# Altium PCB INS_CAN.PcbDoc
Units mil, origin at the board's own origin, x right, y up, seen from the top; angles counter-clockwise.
Board outline 1181.1 x 1181.1 mil, 2 copper layers (Top Layer, Bottom Layer), stack 62.992 mil thick; 50 components, 37 nets, 209 pads, 111 vias.
Unrouted connection lines stored in the file: 32.
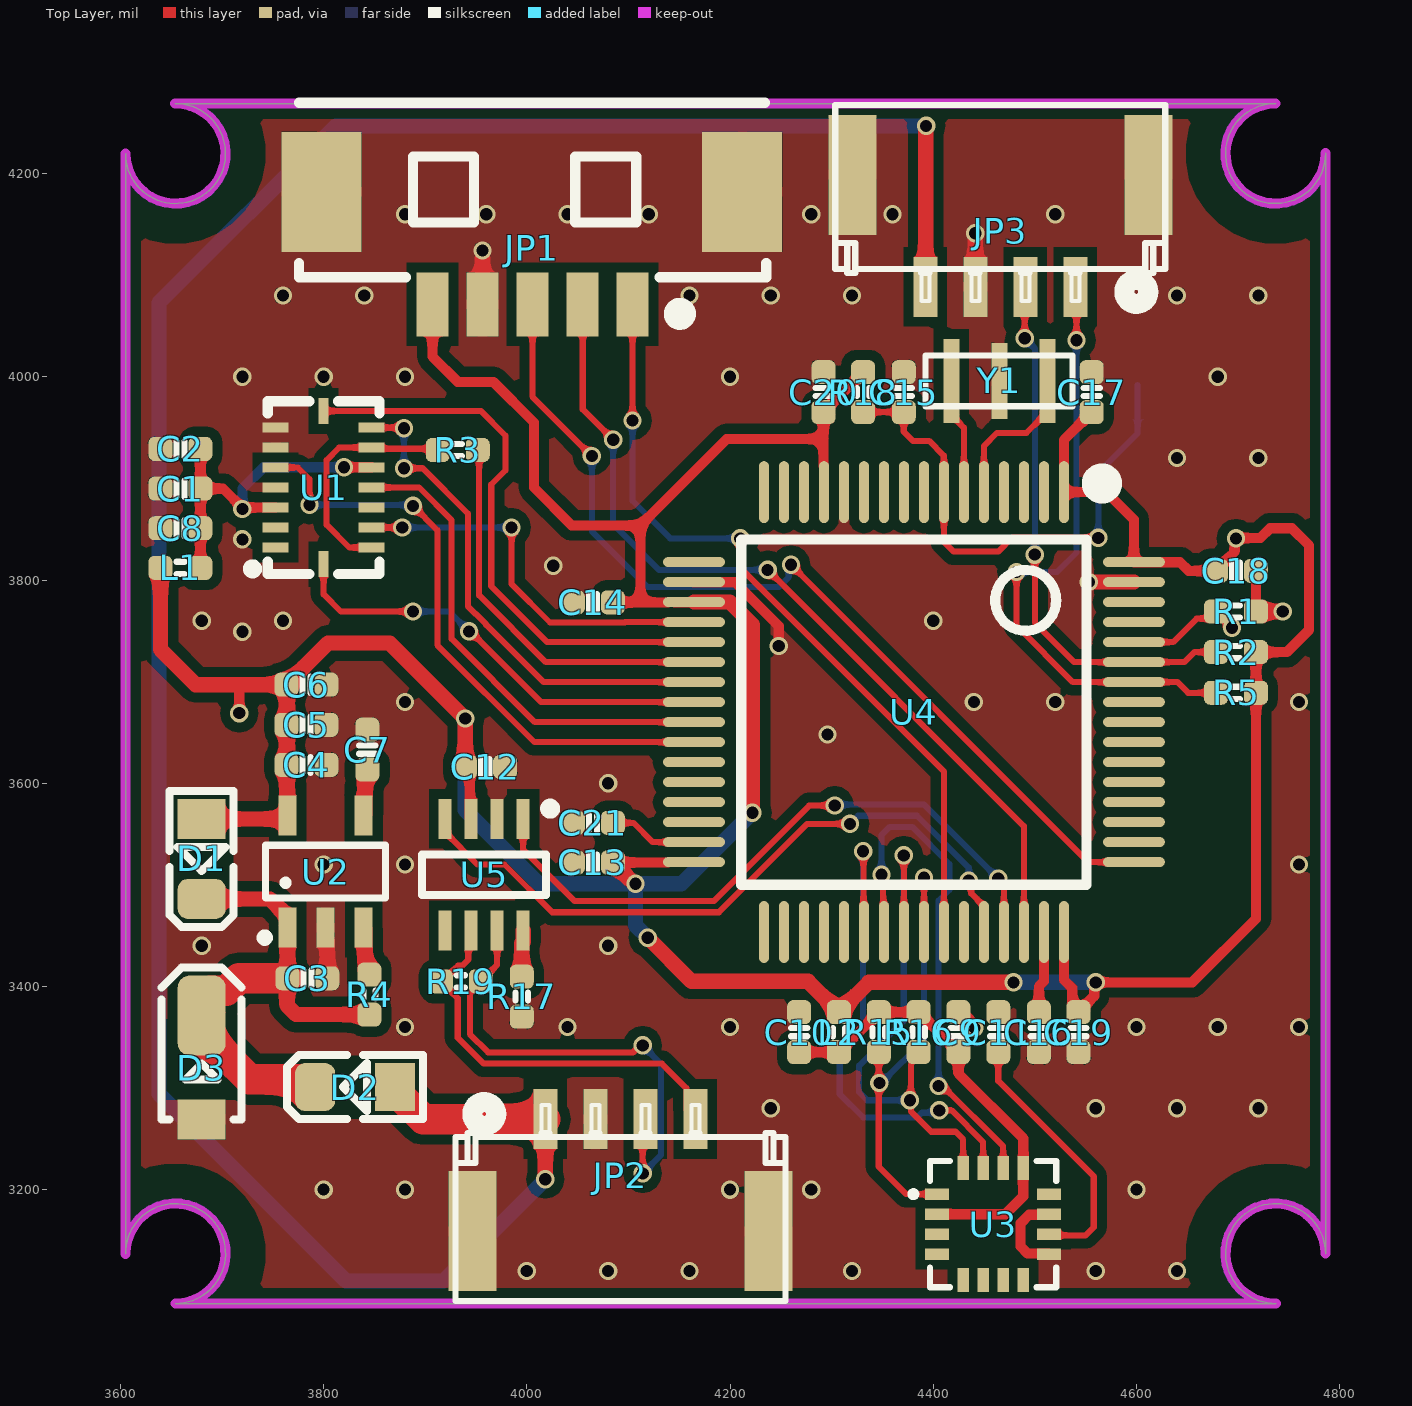
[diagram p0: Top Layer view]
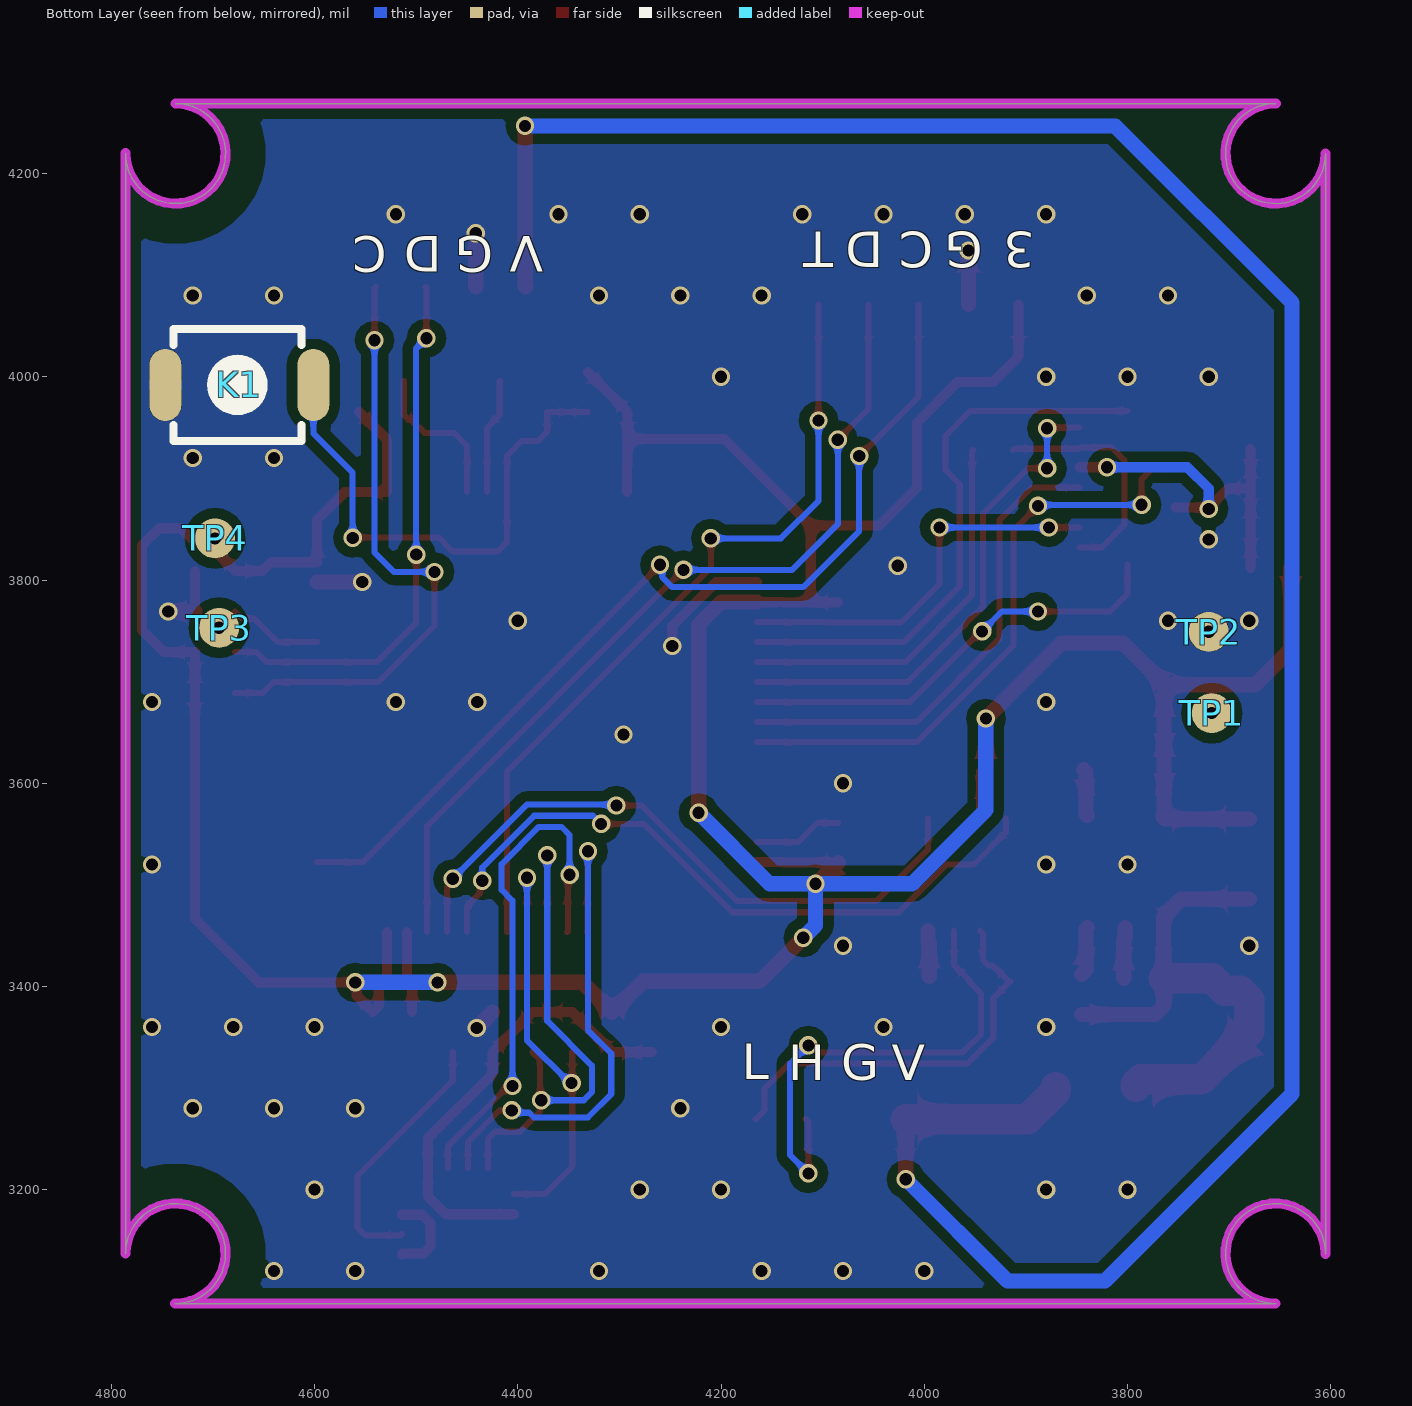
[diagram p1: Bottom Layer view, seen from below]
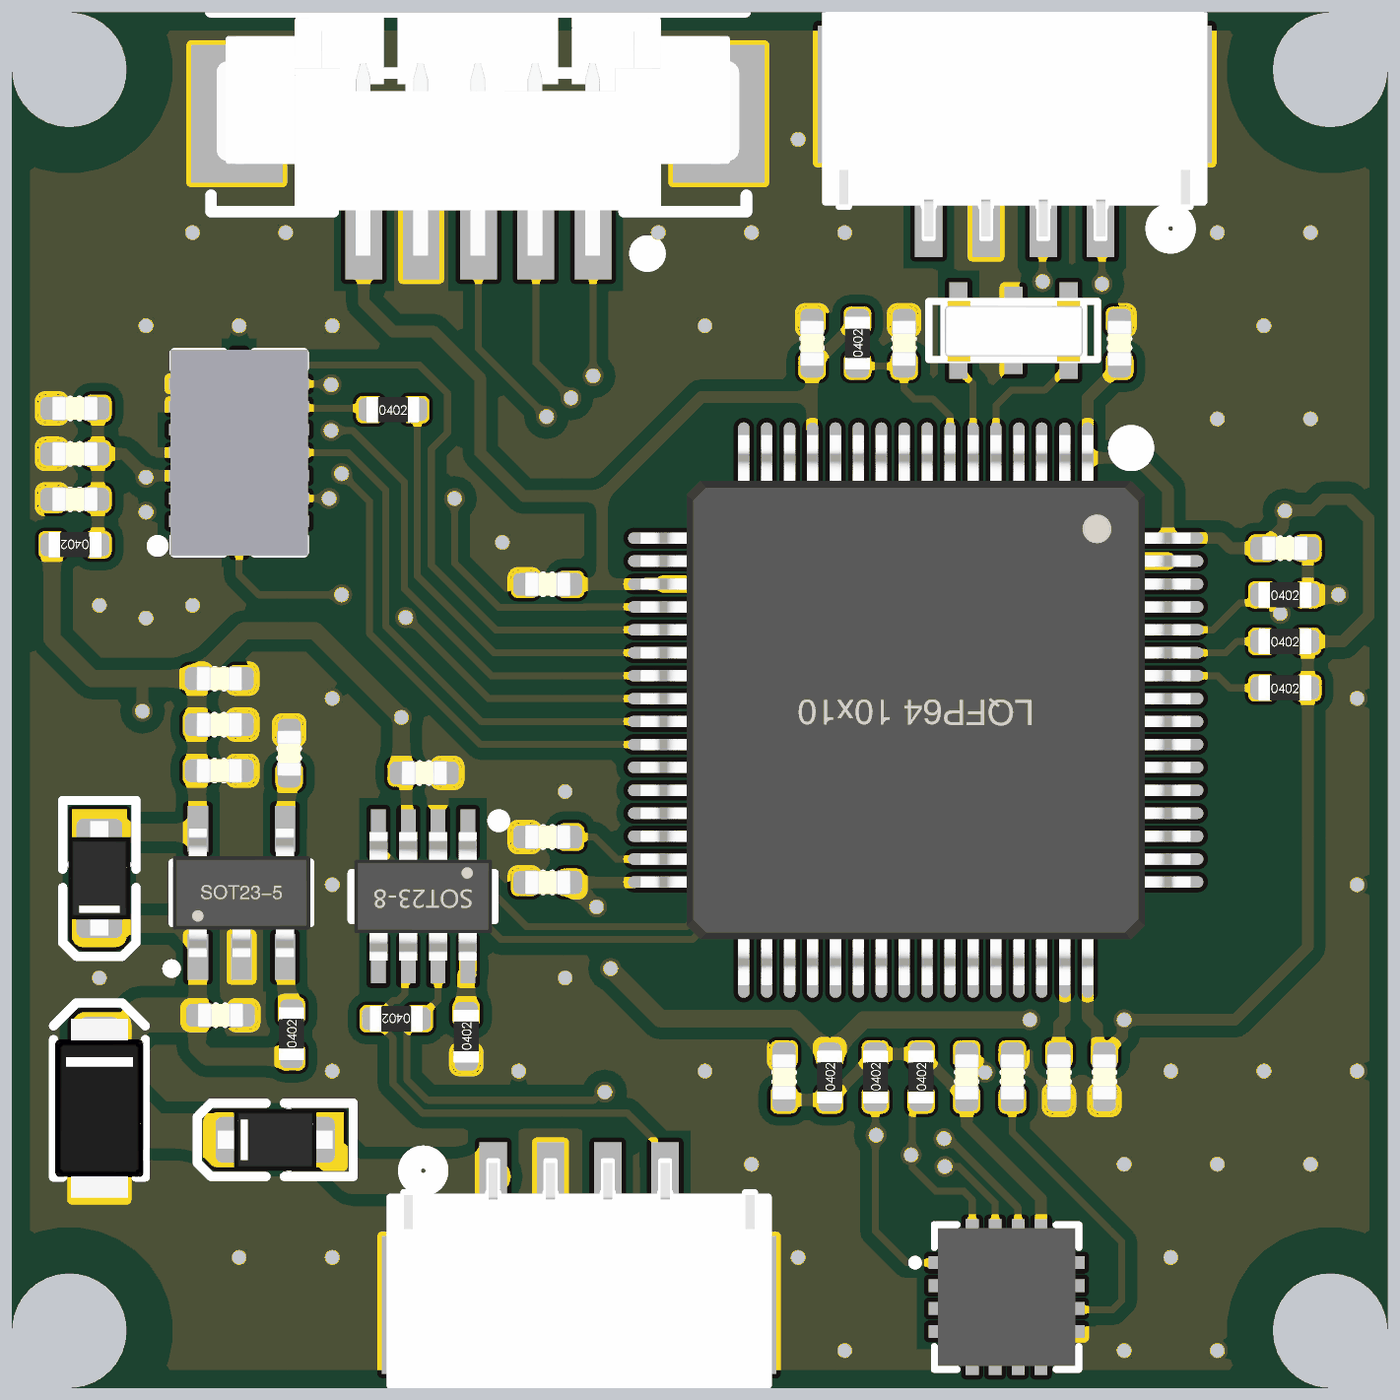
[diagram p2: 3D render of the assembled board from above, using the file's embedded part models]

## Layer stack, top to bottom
Top Solder: solder mask 0.4, Solder Resist, Dk 3.5
Top Layer: signal copper 1.9685
Dielectric 1: dielectric 59.0551, FR-4, Dk 4.8
Bottom Layer: signal copper 1.9685
Bottom Solder: solder mask 0.4, Solder Resist, Dk 3.5

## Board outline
3605,3136.9 3605,4219.79 ccw(c3654.21,4219.79) 3654,4269 4736.89,4269 ccw(c4736.89,4219.79) 4786.1,4220 4786.1,3137.11 ccw(c4736.89,3137.11) 4737.1,3087.9 3654.21,3087.9 ccw(c3654.21,3137.11)

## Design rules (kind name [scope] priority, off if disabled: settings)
AssemblyTestPointUsage [All] p1 off:
AssemblyTestpoint [All] p1 off: testpointundercomponent=TRUE minsize=40 maxsize=100 preferedsize=60 minholesize=0 maxholesize=40 preferedholesize=32 testpointgrid=1 usegrid=TRUE gridtolerance=0.01 allowsidetop=TRUE allowsidebottom=TRUE
Clearance Clearance_1 [InPolygon] p1: gap=10 ignorepadtopadclearanceinfootprint=FALSE
Clearance [All] p2: gap=5 ignorepadtopadclearanceinfootprint=FALSE
ComponentClearance [All] p1 off: gap=10 collisioncheckmode=3 verticalgap=10 showdistances=FALSE
DiffPairsRouting [All] p1 off: maxlimit=10 minlimit=6 mostfreqgap=6 toplayer_minwidth=6 toplayer_maxwidth=15 toplayer_prefwidth=6 bottomlayer_minwidth=6 bottomlayer_maxwidth=15 bottomlayer_prefwidth=6 maxuncoupledlength=500
FabricationTestPointUsage [All] p1 off: valid=0 allowmultiple=FALSE
FabricationTestpoint [All] p1 off: side=3 testpointundercomponent=TRUE minsize=40 maxsize=100 preferedsize=60 minholesize=0 maxholesize=40 preferedholesize=32 testpointgrid=1 allowsidetop=TRUE allowsidebottom=TRUE usegrid=TRUE gridtolerance=0.01
FanoutControl Fanout_BGA [IsBGA] p1 off: bgadir=Out bgaviamode=Centered fanoutstyle=Auto fanoutdirection=Alternating viagrid=1 // Fanout_BGA (Default Rule)
FanoutControl Fanout_LCC [IsLCC] p2 off: bgadir=Out bgaviamode=Centered fanoutstyle=Auto fanoutdirection=Alternating viagrid=1 // Fanout_LCC (Default Rule)
FanoutControl Fanout_SOIC [IsSOIC] p3 off: bgadir=Out bgaviamode=Centered fanoutstyle=Auto fanoutdirection=Alternating viagrid=1 // Fanout_SOIC (Default Rule)
FanoutControl Fanout_Small [(CompPinCount < 5)] p4 off: bgadir=Out bgaviamode=Centered fanoutstyle=Auto fanoutdirection=OutThenIn viagrid=1 // Fanout_Small (Default Rule)
FanoutControl Fanout_Default [All] p5 off: bgadir=Out bgaviamode=Centered fanoutstyle=Auto fanoutdirection=Alternating viagrid=1 // Fanout_Default (Default Rule)
Height [All] p1 off: minheight=0 maxheight=1000 prefheight=500
HoleSize [All] p1 off: absolutevalues=TRUE maxlimit=100 minlimit=1 maxpercent=80.000 minpercent=20.000
HoleToHoleClearance [All] p1 off: gap=10 allowstackedmicrovias=TRUE
LayerPairs [All] p1 off: enforce=TRUE
MinimumSolderMaskSliver [All] p1 off: minsoldermaskwidth=10
NetAntennae [All] p1 off: netantennaetolerance=0
PasteMaskExpansion [All] p1 off: expansion=0
PlaneClearance [All] p1 off: clearance=30
PlaneConnect [All] p1 off: planeconnectstyle=Direct reliefexpansion=10 reliefentries=4 reliefconductorwidth=10 reliefairgap=5
PolygonConnect [All] p1 off: connectstyle=Direct reliefconductorwidth=10 reliefentries=4 polygonreliefangle="90 Angle" airgapwidth=10
RoutingCorners [All] p1 off: cornerstyle=45-Degree minsetback=100 maxsetback=100
RoutingLayers [All] p1 off: top layer_v5=TRUE bottom layer_v5=TRUE
RoutingPriority [All] p1 off: routingpriority=0
RoutingTopology [All] p1 off: topology=Shortest
RoutingVias [All] p1 off: holewidth=10 width=18 viastyle="Through Hole" minholewidth=5 minwidth=5 maxholewidth=100 maxwidth=100
SilkToSilkClearance [All] p1 off: silktosilkclearance=10
SilkToSolderMaskClearance [IsPad] p1 off: minsilkscreentomaskgap=10 clearancetoexposedcopper=TRUE
SolderMaskExpansion [All] p1 off: expansion=4 istentingtop=FALSE
Width [All] p1 off: maxlimit=1000 minlimit=5 preferedwidth=10
4 further rules are at their usual default settings.

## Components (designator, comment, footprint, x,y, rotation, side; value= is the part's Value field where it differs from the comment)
C1 "10uF" C0402 3659,3890 r180 top value=0.1u
C2 "0.1uF" C0402 3659,3929 r180 top value=0.1u
C3 "1uF/25V" C0402 3784,3408 r180 top value=0.1u
C4 "0.1uF/50V" C0402 3783,3618 r180 top value=0.1u
C5 "1uF/25V" C0402 3783,3657.5 r180 top value=0.1u
C6 "0.1uF/50V" C0402 3783,3697 r180 top value=0.1u
C7 "10nF/50V" C0402 3843,3633 r270 top value=0.1u
C8 "0.1uF" C0402 3659,3851 r180 top value=0.1u
C9 "0.1uF" C0402 4424.8,3355 r90 top value=0.1u
C10 "0.1uF" C0402 4268,3355 r90 top value=0.1u
C11 "4.7uF" C0402 4464,3355 r90 top value=0.1u
C12 "0.1uF/50V" C0402 3959,3616 r180 top value=0.1u
C13 "0.1uF" C0402 4065,3522 r180 top value=0.1u
C14 "0.1uF" C0402 4065,3778 r180 top value=0.1u
C15 "0.1uF/50V" C0402 4371,3985 r270 top value=0.1u
C16 "2.2uF" C0402 4504,3355 r270 top value=0.1u
C17 "0.1uF" C0402 4556,3985 r90 top value=0.1u
C18 "0.1uF" C0402 4698,3809 r0 top value=0.1u
C19 "0.1uF" C0402 4543,3355 r270 top value=0.1u
C20 "0.1uF" C0402 4292,3985 r90 top value=0.1u
C21 "2.2uF" C0402 4065,3561 r180 top value=0.1u
D1 "1N5819" D_SOD323 3680,3525.5 r270 top
D2 "1N5819" D_SOD323 3831,3301 r180 top
D3 "SMFJ5.0A" D_SOD123A 3680,3328 r90 top
JP1 "HDR-1X5" "MX 1.25-WS-5P" 4005,4182 r180 top
JP2 "SWD" GH1.25-WS-4P 4092,3171 r180 top
JP3 "SWD" GH1.25-WS-4P 4466,4187 r0 top
K1 "6x6x5" SWPBS_SPST_3X2X1 4676,3992 r180 bottom
L1 "60R 25% 3A" R0402 3659,3812 r180 top
L2 "60R 25% 3A" R0402 4307.2,3355 r90 top
R1 "10K" R0402 4698,3769 r0 top value=22R
R2 "4.7K" R0402 4698,3729 r0 top value=22R
R3 "33R" R0402 3932,3928 r0 top value=22R
R4 "100K" R0402 3845,3392 r90 top value=22R
R5 "4.7K" R0402 4698,3689 r0 top value=22R
R15 "4.7K" R0402 4346.4,3355 r90 top value=22R
R16 "4.7K" R0402 4385.6,3355 r90 top value=22R
R17 "0R" R0402 3995,3390 r90 top value=22R
R18 "10K" R0402 4331,3985 r90 top value=22R
R19 "120R/NC" R0402 3935,3405 r180 top value=22R
TP1 "TEST" "TEST 1" 3717,3669 r270 bottom
TP2 "TEST" "TEST 1" 3720,3749 r270 bottom
TP3 "TEST" "TEST 1" 4694,3753 r0 bottom
TP4 "TEST" "TEST 1" 4698,3841 r0 bottom
U1 "BMI088" "QFN16 BMI" 3800,3891 r0 top
U2 "LP5907 3V3" SOT23-5L 3802,3513 r0 top
U3 "IST8310" QFN50_16T_3X3_IST 4459,3166 r270 top
U4 "STM32F405RGT6V" "LQFP64 10x10_L" 4381,3670 r180 top
U5 "MAX3051EKA+T" SOT23-8L 3958,3510 r180 top
Y1 "8MHz" CSTCE3213 4437.24,3921 r270 top

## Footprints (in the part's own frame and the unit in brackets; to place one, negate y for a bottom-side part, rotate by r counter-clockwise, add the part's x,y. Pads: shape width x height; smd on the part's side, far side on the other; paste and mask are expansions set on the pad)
C0402 [mm] "CHIP Capacitor, 1.0X0.5mm, 0402"
  rrect50% 0.6x0.6 smd paste-0.05 mask+0.075: 1(-0.5,0) 2(0.5,0)
  silkscreen extent -0.1,-0.2 0.1,0.2, body extent -0.5,-0.26 0.5,0.27, height 0.36
CSTCE3213 [mm]
  rect 2.1x0.4 smd: 1(-1.905,1.905) 3(-1.905,-0.495)
  rect 1.9x0.4 smd: 2(-1.905,0.705)
  silkscreen extent -2.54,-1.14 -1.27,2.54, body extent -2.55,-0.89 -1.23,2.31, height 0.9
D_SOD123A [mm] "PowerDI-123, SOD123, DO-213AA, 1206D"
  rect 1x1.2 smd paste-0.1 mask+0.1: 1(-1.5,0)
  rrect50% 2x1.2 smd paste-0.1 mask+0.1: 2(1.1,0)
  Top Layer pour cut-out: -1.016,1.1 -1.016,-1.1 1.016,-1.1 1.016,1.1
  silkscreen extent -1.5,-1 2.3,1, body extent -1.95,-0.97 1.95,0.96, height 1
D_SOD323 [mm] "DIODE0805, SOD-323, SC-76, DL-35, 0805 similar size"
  rect 1x1.2 smd paste-2 mask+0.075: 1(-1,0)
  rrect50% 1x1.2 smd paste-2 mask+0.075: 2(1,0)
  Top Layer pour cut-out: -0.5,0.8 0.5,0.8 0.5,-0.8 -0.5,-0.8
  silkscreen extent -1.7,-0.8 1.7,0.8, body extent -1.25,-0.68 1.25,0.67, height 1
GH1.25-WS-4P [mm] "A1257WR-S-4P"
  rect 1.2x3 smd: 0(-3.7,0.3) 0(3.7,0.3)
  rect 0.6x1.5 smd: 1(1.875,-2.5) 2(0.625,-2.5) 3(-0.625,-2.5) 4(-1.875,-2.5)
  silkscreen extent -4.13,-2.93 4.12,2.05, body extent -4.12,-2.8 4.12,2.1, height 4.4
"LQFP64 10x10_L" [mm] "64脚，体宽10x10mm，脚距0.5mm"
  oval 0.25x1.55 smd: 1(-3.75,-5.5) 2(-3.25,-5.5) 3(-2.75,-5.5) 4(-2.25,-5.5) 5(-1.75,-5.5) 6(-1.25,-5.5) 7(-0.75,-5.5) 8(-0.25,-5.5) 9(0.25,-5.5) 10(0.75,-5.5) 11(1.25,-5.5) 12(1.75,-5.5) 13(2.25,-5.5) 14(2.75,-5.5) 15(3.25,-5.5) 16(3.75,-5.5) 33(3.75,5.5) 34(3.25,5.5) 35(2.75,5.5) 36(2.25,5.5) 37(1.75,5.5) 38(1.25,5.5) 39(0.75,5.5) 40(0.25,5.5) 41(-0.25,5.5) 42(-0.75,5.5) 43(-1.25,5.5) 44(-1.75,5.5) 45(-2.25,5.5) 46(-2.75,5.5) 47(-3.25,5.5) 48(-3.75,5.5)
  oval 1.55x0.25 smd: 17(5.5,-3.75) 18(5.5,-3.25) 19(5.5,-2.75) 20(5.5,-2.25) 21(5.5,-1.75) 22(5.5,-1.25) 23(5.5,-0.75) 24(5.5,-0.25) 25(5.5,0.25) 26(5.5,0.75) 27(5.5,1.25) 28(5.5,1.75) 29(5.5,2.25) 30(5.5,2.75) 31(5.5,3.25) 32(5.5,3.75) 49(-5.499,3.75) 50(-5.499,3.25) 51(-5.499,2.75) 52(-5.499,2.25) 53(-5.499,1.75) 54(-5.499,1.25) 55(-5.499,0.75) 56(-5.499,0.25) 57(-5.499,-0.25) 58(-5.499,-0.75) 59(-5.499,-1.25) 60(-5.499,-1.75) 61(-5.499,-2.25) 62(-5.499,-2.75) 63(-5.499,-3.25) 64(-5.499,-3.75)
  silkscreen extent -4.95,-5.96 4.32,4.32, body extent -6,-6 6,6, height 1.45
"MX 1.25-WS-5P" [mm] "长：11.4mm，宽：4.2mm，高：3.4mm"
  rect 2x3 smd: 0(-5.257,0) 0(5.257,0)
  rect 0.8x1.6 smd: 1(-2.514,2.811) 2(-1.264,2.811) 3(-0.014,2.811) 4(1.236,2.811) 5(2.486,2.811)
  silkscreen extent -5.86,-2.23 5.83,3.25, body extent -5.7,-2.1 5.7,3.09, height 3.4
"QFN16 BMI" [mm] "16脚，长x宽x高：4x4x0.8mm，脚距：0.65mm"
  rect 0.65x0.25 smd: 1(-1.2,-1.498) 2(-1.2,-0.998) 3(-1.2,-0.498) 4(-1.2,0.002) 5(-1.2,0.502) 6(-1.2,1.002) 7(-1.2,1.502) 9(1.2,1.502) 10(1.2,1.002) 11(1.2,0.502) 12(1.2,0.002) 13(1.2,-0.498) 14(1.2,-0.998) 15(1.2,-1.498)
  rect 0.25x0.65 smd: 8(0,1.915) 16(0,-1.915)
  silkscreen extent -1.89,-2.16 1.4,2.16, body extent -1.5,-2.25 1.5,2.25, height 0.88
QFN50_16T_3X3_IST [mm] "RGT PVQFN (TI), 16-lead, pitch: 0.5mm, 3x3mm"
  rect 0.28x0.6 smd: 1(-0.75,-1.4) 2(-0.25,-1.4) 3(0.25,-1.4) 4(0.75,-1.4) 9(0.75,1.4) 10(0.25,1.4) 11(-0.25,1.4) 12(-0.75,1.4)
  rect 0.6x0.28 smd: 5(1.4,-0.75) 6(1.4,-0.25) 7(1.4,0.25) 8(1.4,0.75) 13(-1.4,0.75) 14(-1.4,0.25) 15(-1.4,-0.25) 16(-1.4,-0.75)
  silkscreen extent -1.58,-2.07 1.58,1.58, body extent -1.5,-1.5 1.5,1.5, height 1
R0402 [mm] "CHIP Resistor, 1.0X0.5mm, 0402"
  rrect50% 0.6x0.6 smd paste-0.05 mask+0.075: 1(-0.5,0) 2(0.5,0)
  silkscreen extent -0.1,-0.15 0.1,0.15, body extent -0.57,-0.27 0.58,0.28, height 0.41
SOT23-5L [mm] "3x1.6x1.1mm(长宽高)"
  rect 0.45x1 smd: 1(-0.95,-1.4) 2(0,-1.4) 3(0.95,-1.4) 4(0.95,1.4) 5(-0.95,1.4)
  silkscreen extent -1.6,-1.73 1.5,0.66, body extent -1.5,-1.4 1.5,1.4, height 1.15
SOT23-8L [mm] "3x1.6x1.1mm(长宽高)"
  rect 0.325x1 smd: 1(-0.975,-1.397) 2(-0.325,-1.397) 3(0.325,-1.397) 4(0.975,-1.397) 5(0.975,1.397) 6(0.325,1.397) 7(-0.325,1.397) 8(-0.975,1.397)
  silkscreen extent -1.78,-1.78 1.55,0.51, body extent -1.5,-1.4 1.5,1.4, height 1.15
SWPBS_SPST_3X2X1 [mm] "SWITCH, PUSHBUTTON, SMD, SPST, 3X2.5mm"
  oval 0.8x1.8 smd mask+0.1: 1(-1.8,0) 2(1.9,0)
  silkscreen extent -1.6,-1.4 1.6,1.4, body extent -2,-1.25 2,1.25, height 1.6
"TEST 1" [mm] "测试点1mm"
  round 1 smd paste-1: 1(0,0)

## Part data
C1 C2 C3 C4 C5 C6 C7 C8 C9 C10 C11 C12 C13 C14 C15 C16 C17 C18 C19 C20 C21: library part 电容-0402, "Capacitor"
D1 D2: library part Diode_SMA, "Diode"
D3: library part SMBJ28CA
JP1: library part "Header 5", "5P接插件"
JP2 JP3: library part "Header 1*4"
K1: library part "TSW DIP-6x6_V", "侧按直插6x6轻触开关"
L1 L2: library part L, "小功率贴片电感"
R1 R2 R3 R4 R5 R15 R16 R17 R18 R19: library part 电阻-0402, "Resistor"
TP1 TP2 TP3 TP4: "测试点"
U1: BOM_JLCPCB Part Class="Extended Part", BOM_Manufacturer="Bosch Sensortec"
U2: library part LP2992, "LDO"
U4: JLCPCB Part Class=扩展库, Manufacturer=ST(意法半导体)
U5: BOM_JLCPCB Part Class="Extended Part", BOM_Manufacturer=MAXIM
Y1: library part 晶振-3Pin, "村田贴片"

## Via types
v1: diameter 18, hole 12, Top Layer to Bottom Layer, tented both sides, 111 vias

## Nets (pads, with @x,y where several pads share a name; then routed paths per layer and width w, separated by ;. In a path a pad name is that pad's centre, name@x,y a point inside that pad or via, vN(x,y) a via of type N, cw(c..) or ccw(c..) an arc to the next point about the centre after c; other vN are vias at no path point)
3V3: C4.2 C5.2 C6.2 C12.2 C13.1 C14.1 C17.1 C18.1 C19.1 C20.1 D1.1 JP1.5 L1.2 L2.2 R2.2 R5.2 R18.2 TP1.1 TP4.1 U2.5 U4.1 U4.13 U4.19 U4.32 U4.48 U4.64 U5.3 | length 4124
  Top Layer w10: v1(3717,3669) 3717,3695.34 3718.66,3697 ; JP1.5 3907.12,4019.88 3932,3995 3967,3995 4007,3955 4007,3891 4044.27,3853.73 4111.73,3853.73 ; C12.2 3943.81,3611.51 3943.81,3566.4 U5.3 ; C13.1 4138.67,3522 4139.04,3522.37 U4.32 ; C14.1 4111.73,3778 ; U4.19 4139.04,3778.27 4138.77,3778 4111.73,3778 ; U4.13 4292.41,3911.96 4292,3912.36 4292,3938.84 ; R18.2 4331,4004.5 4292,3965.5 C20.1 4292,3938.84 ; U4.48 4528.63,3406.37 4536.75,3398.25 4536.75,3380.94 C19.1 4543,3375.18 4558.47,3390.64 4558.47,3402.47 v1(4560,3404) 4655,3404 4717.69,3466.68 R5.2 R2.2 4748,3729 4770,3751 4770,3834 4753,3851 4731.58,3851 4722,3841.42 4698.42,3841.42 v1(4698,3841) 4696.47,3839.47 4696.47,3827.64 4678.31,3809.49 C18.1 4651.5,3809 4642.94,3817.56 4597.59,3817.56 U4.64 4597.51,3859.49 4570.48,3886.52 U4.1 4528.63,3937.94 C17.1 ; 4111.73,3778 4111.73,3853.73 ; 4111.73,3853.73 4196.84,3938.84 4292,3938.84
  Top Layer w15: L1.2 3639.32,3731.68 3674,3697 3718.66,3697 C6.2 ; D1.1 3763.24,3564.87 3764.6,3566.23 U2.5 3763.96,3568.76 3763.96,3696.36 C6.2 ; C12.2 v1(3939.32,3663.68) 3865,3738 3804.32,3738 C6.2 ; C13.1 4105.11,3501.57 4106.43,3501.57 v1(4107,3501) ; v1(4119,3448) 4162,3405 4276.89,3405 L2.2 4336.52,3404 v1(4479,3404) ; U4.19 4199.73,3778.27 4222,3756 v1(4222,3571)
  Bottom Layer w15: v1(3939.32,3663.68) 3939.32,3573.68 4012,3501 v1(4107,3501) ; v1(4119,3448) 4107,3460 v1(4107,3501) ; v1(4222,3571) 4152,3501 v1(4107,3501) ; v1(4479,3404) v1(4560,3404)
5V: C3.2 D1.2 D2.2 D3.2 R4.1 U2.1 | length 524.6
  Top Layer w15: D1.2 3747.18,3486.13 3764.46,3468.85 3764.46,3408.14 C3.2 3764,3407.68 3764,3381.1 3772.79,3372.32 R4.1
  Top Layer w30: C3.2 3716.69,3408 3704.37,3395.68 3688.62,3395.68 3680,3387.06 D3.2 3680,3355.56 3726.94,3308.61 3786.94,3308.61 3791.63,3303.93 D2.2
AS_SCL: JP3.1 R5.1 U4.58 | length 605.6
  Top Layer w6: v1(4482,3808) 4482,3755 4537.47,3699.53 U4.58 4640.47,3699.53 4651,3689 R5.1 ; JP3.1 4541,4087.39 v1(4541,4036)
  Bottom Layer w6: v1(4482,3808) 4522,3808 4541,3827 v1(4541,4036)
AS_SDA: JP3.2 R2.1 U4.59 | length 533.4
  Top Layer w6: v1(4490,4038) 4490,4087.97 JP3.2 ; v1(4500,3825) 4500,3758 4538.78,3719.22 U4.59 4647.22,3719.22 4657,3729 R2.1
  Bottom Layer w6: v1(4490,4038) 4500,4028 v1(4500,3825)
BOOT0: R1.1 TP3.1 U4.60 | length 115.8
  Top Layer w6: U4.60 4636.1,3738.9 4659.18,3761.98 4671.3,3761.98 R1.1 4678.31,3768.84 4694,3753.16 v1(4694,3753)
CAN_D: U4.45 U5.1 | length 643.3
  Top Layer w6: U5.1 3996.39,3534.67 4047.06,3484 4184,3484 4278,3578 v1(4303,3578) ; v1(4464,3506) 4464,3502.75 4469.57,3497.18 U4.45
  Bottom Layer w6: v1(4303,3578) 4304,3579 4391,3579 v1(4464,3506)
CAN_H: JP2.3 R19.1 U5.7 | length 488.9
  Top Layer w6: U5.7 3970.8,3421.11 R19.1 3954.68,3403.43 3944,3392.74 3944,3353 3962,3335 4104.49,3335 4111.49,3342 v1(4114,3342) ; v1(4114,3216) 4114,3266.82 JP2.3
  Bottom Layer w6: v1(4114,3216) 4132,3234 4132,3324 v1(4114,3342)
CAN_L: JP2.4 R19.2 U5.6 | length 407.9
  Top Layer w6: U5.6 3942.31,3452.11 3942.31,3426.31 3936.5,3420.5 3932.39,3420.5 3916.89,3405 R19.2 3932,3388.32 3932,3349.44 3957.44,3324 4133,3324 4157.01,3299.99 4157.01,3278.24 JP2.4
CAN_R: U4.44 U5.4 | length 691.4
  Top Layer w6: U5.4 3919.61,3551.71 3951.33,3520 3978,3520 4025,3473 4189,3473 4276,3560 v1(4318,3560) ; v1(4435,3504) 4437.3,3501.7 4437.3,3491.67 4449.89,3479.07 U4.44
  Bottom Layer w6: v1(4318,3560) 4326,3568 4384,3568 4435,3517 v1(4435,3504)
GND: C1.2 C2.2 C3.1 C4.1 C5.1 C6.1 C7.1 C8.2 C9.2 C10.2 C11.2 C12.1 C13.2 C14.2 C15.1 C16.2 C17.2 C18.2 C19.2 C20.2 C21.2 D3.1 JP1.0 JP1.4 JP2.0 JP2.2 JP3.0 JP3.3 K1.1 R1.2 R17.1 TP2.1 U1.4 U1.6 U1.7 U2.2 U3.9 U3.11 U4.12 U4.18 U4.63 U5.2 Y1.2 | length 496.5
  Top Layer w10: U4.18 4164.55,3797.88 4204.87,3797.88 4248,3754.75 v1(4248,3735) ; U3.9 4513.61,3136.98 4493.02,3136.98 4486,3144 4486,3167 4494.33,3175.33 4513.61,3175.33 U3.11 ; R1.2 C18.2
  Top Layer w15: U2.2 3802,3447.06 3803.68,3445.37 C3.1 ; JP1.4 v1(3956.33,4124.33) ; C9.2 v1(4440.48,3359) ; JP3.3 v1(4441.39,4141.39) ; v1(4553.04,3797.96) U4.63 ; R1.2 v1(4744,3769)
  other v1: 4000,3120 4080,3120 4160,3120 4320,3120 4560,3120 4640,3120 3800,3200 3880,3200 4200,3200 4280,3200 4600,3200 4240,3280 4560,3280 4640,3280 4720,3280 3880,3360 4040,3360 4200,3360 4600,3360 4680,3360 4760,3360 3680,3440 4080,3440 3800,3520 3880,3520 4760,3520 4080,3600 4296,3648 3880,3680 4440,3680 4520,3680 4760,3680 3720,3749 3680,3760 3760,3760 4400,3760 4026,3814 3720,3840 4640,3920 4720,3920 3720,4000 3800,4000 3880,4000 4200,4000 4680,4000 3760,4080 3840,4080 4160,4080 4240,4080 4320,4080 4640,4080 4720,4080 3880,4160 3960,4160 4040,4160 4120,4160 4280,4160 4360,4160 4520,4160
IMU_CS1_Accel: U1.14 U4.20 | length 390.4
  Top Layer w6: U1.14 v1(3877.29,3851.71) ; v1(3985,3851.71) 3983,3849.71 3985,3847.71 3985,3796 4022.81,3758.19 4096.35,3758.19 4096.75,3758.59 U4.20
  Bottom Layer w6: v1(3877.29,3851.71) v1(3985,3851.71)
IMU_CS1_Gyro: U1.5 U4.26 | length 604.7
  Top Layer w6: U1.5 3774.56,3910.76 3786,3899.32 v1(3786,3874) ; v1(3888,3873) 3912,3849 3912,3736 4007.52,3640.48 U4.26
  Bottom Layer w6: v1(3786,3874) 3887,3874 v1(3888,3873)
IMU_INT1_Accel: U1.16 U4.24 | length 438.1
  Top Layer w6: U1.16 3800,3786 3817,3769 v1(3888,3769) ; v1(3943,3749.48) 3944.52,3749.48 4014.15,3679.85 U4.24
  Bottom Layer w6: v1(3888,3769) 3923.48,3769 v1(3943,3749.48)
IMU_INT1_Gyro: U1.12 U4.25 | length 481.4
  Top Layer w6: U1.12 3893.96,3891.08 3926,3859.04 3926,3742 4007.84,3660.16 U4.25
IMU_MISO: R3.2 U4.22 | length 382.3
  Top Layer w6: R3.2 3953,3926.68 3953,3785 4018.78,3719.22 U4.22
IMU_MOSI: U1.9 U4.23 | length 498
  Top Layer w6: U1.9 3847.31,3950.07 3878.32,3950.07 v1(3879,3949.39) ; v1(3879,3910) 3897.49,3910 3942,3865.49 3942,3774 3949.52,3766.48 3950.04,3766.48 3960,3756.52 3960,3756 4016.47,3699.53 U4.23
  Bottom Layer w6: v1(3879,3910) v1(3879,3949.39)
IMU_SCK: U1.8 U4.21 | length 565.2
  Top Layer w6: U1.8 3954.61,3966.39 3979,3942 3979,3908 3965,3894 3965,3794 4020.1,3738.9 U4.21
IST_DRDY: U3.15 U4.38 | length 520.6
  Top Layer w6: v1(4331,3533) 4331.39,3532.61 4331.39,3453.87 U4.38 ; v1(4406,3278) 4418,3278 4449.16,3246.84 U3.15
  Bottom Layer w6: v1(4331,3533) 4331,3357 4308,3334 4308,3294 4331,3271 4384.04,3271 4388.75,3275.7 4403.7,3275.7 v1(4406,3278)
IST_RSTN: U3.14 U4.39 | length 514.6
  Top Layer w6: v1(4349,3510) 4350.73,3508.27 4350.73,3454.22 U4.39 ; v1(4405.28,3302) 4409.56,3302 4468.84,3242.72 U3.14
  Bottom Layer w6: v1(4349,3510) 4349,3549 4357,3557 4379.44,3557 4416,3520.44 4416,3495 4405.28,3484.28 v1(4405.28,3302)
IST_SCL: R15.1 U3.1 U4.41 | length 456.6
  Top Layer w6: v1@4346.4,3305 R15.1 ; v1(4347,3305) 4346.4,3304.4 4346.4,3222.6 4373.47,3195.53 U3.1 ; U4.41 4390.92,3453.57 4390.92,3506.92 v1(4391,3507)
  Bottom Layer w6: v1(4347,3305) 4349,3305 4391,3347 v1(4391,3507)
IST_SDA: R16.1 U3.16 U4.40 | length 532.8
  Top Layer w6: v1(4371,3529) 4371.07,3528.93 4371.07,3453.56 U4.40 ; R16.1 4378.58,3328.3 4378.58,3323.57 4378,3322.99 4378,3277 4398,3257 4422,3257 4429.47,3249.53 U3.16
  Bottom Layer w6: v1(4371,3529) 4371,3366 4327,3322 4327,3296 4335,3288 v1(4377,3288)
NetC1_1: C1.1 C2.1 C8.1 L1.1 U1.3 U1.11 | length 354.8
  Top Layer w10: L1.1 C8.1 C1.1 ; C2.1 C1.1 ; U1.3 3719.6,3871.4 3701,3890 C1.1 ; v1(3820,3911) 3847,3911 U1.11
  Bottom Layer w10: v1(3720,3870) 3720,3890 3741,3911 v1(3820,3911)
NetC7_2: C7.2 U2.4 | length 46.7
  Top Layer w15: U2.4 3840.76,3569.48 3840.76,3611.07 C7.2
NetC9_1: C9.1 C10.1 L2.1 R15.2 R16.2 U3.2 U3.13 | length 449.8
  Top Layer w10: C10.1 L2.1 4307.2,3335.4 4346.4,3374.6 R15.2 R16.2 4385.6,3374.6 4424.8,3335.4 4424.8,3314.2 4488.53,3250.47 U3.13 4488.53,3193.53 4470.84,3175.84 U3.2
NetC11_1: C11.1 U3.10 | length 258.9
  Top Layer w6: C11.1 4464,3307 4558,3213 4558,3163 4550,3155 4515.28,3155 U3.10
NetC16_1: C16.1 U4.47 | length 80.8
  Top Layer w10: C16.1 4504,3400 4508.94,3404.94 U4.47
NetC21_1: C21.1 U4.31 | length 87.6
  Top Layer w6: C21.1 4105,3561 4123.95,3542.05 U4.31
NetR3_1: R3.1 U1.10 U1.15 | length 232.7
  Top Layer w6: U1.15 3825.28,3832.03 3803,3854.31 3803,3918.04 3815.41,3930.45 U1.10 3848.47,3929.22 3911.09,3929.22 R3.1
NetR4_2: R4.2 U2.3 | length 48.5
  Top Layer w15: U2.3 3840.76,3456.52 3840.76,3415.93 R4.2
NetR17_2: R17.2 U5.8 | length 45.9
  Top Layer w15: R17.2 3995,3442.53 3996.39,3443.92 U5.8
NetU4_5: U4.5 Y1.1 | length 153.9
  Top Layer w6: U4.5 4449.89,3931.89 4462.77,3944.77 4491.77,3944.77 4504.66,3957.66 4507.37,3957.66 4512.24,3962.54 Y1.1
NetU4_6: U4.6 Y1.3 | length 114.6
  Top Layer w6: Y1.3 4417.76,3962.54 4430.2,3950.09 U4.6
NRST: C15.2 K1.2 R18.1 U4.7 | length 522
  Top Layer w6: R18.1 C15.2 4371,3946 4380,3937 4396,3937 4410.52,3922.48 U4.7 4410.52,3837.48 4420,3828 4464,3828 4478,3842 4562,3842 v1(4562.5,3841.5)
  Bottom Layer w6: v1(4562.5,3841.5) 4562.5,3905.75 4601.2,3944.44 K1.2
SWCLK: JP1.3 U4.49 | length 941.3
  Top Layer w6: JP1.3 4005.54,3980.46 4062,3924 4062,3922 v1(4064,3922) ; v1(4260,3815) 4552.63,3522.37 U4.49
  Bottom Layer w6: v1(4064,3922) 4064,3848 4119,3793 4248.19,3793 4257.7,3802.51 4257.7,3812.7 v1(4260,3815)
SWDIO: JP1.2 U4.46 | length 860.5
  Top Layer w6: JP1.2 4055,4071.1 4055,3968 v1(4085,3938) ; v1(4237,3810) 4489.26,3557.74 U4.46
  Bottom Layer w6: v1(4085,3938) 4085,3855 4130,3810 v1(4237,3810)
UART1_Tx: JP1.1 U4.42 | length 786.1
  Top Layer w6: v1(4104,3957) JP1.1 ; v1(4210,3841) 4210,3812.19 4410.52,3611.67 U4.42
  Bottom Layer w6: v1(4104,3957) 4104,3878 4141,3841 4208,3841 4209,3842 v1(4210,3841)
VCC: D2.1 JP2.1 JP3.4 | length 2485.2
  Top Layer w15: v1(4018.18,3210.18) JP2.1 ; JP3.4 4392.59,4088.98 4392.59,4246.59 v1(4393,4247)
  Top Layer w30: D2.1 3870.37,3297.06 3898.01,3269.43 JP2.1
  Bottom Layer w15: v1(4018.18,3210.18) 3918,3110 3822,3110 3638,3294 3638,4073 3812,4247 v1(4393,4247)
pads on no net: U1.1 U1.2 U1.13 U3.3 U3.4 U3.5 U3.6 U3.7 U3.8 U3.12 U4.2 U4.3 U4.4 U4.8 U4.9 U4.10 U4.11 U4.14 U4.15 U4.16 U4.17 U4.27 U4.28 U4.29 U4.30 U4.33 U4.34 U4.35 U4.36 U4.37 U4.43 U4.50 U4.51 U4.52 U4.53 U4.54 U4.55 U4.56 U4.57 U4.61 U4.62 U5.5

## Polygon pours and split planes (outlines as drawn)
GND on Top Layer "GND_L01_P000" (solid, remove dead copper, pour order 0): 3605,3136.9 3605,4219.79 ccw(c3654.21,4219.79) 3654,4269 4736.89,4269 ccw(c4736.89,4219.79) 4786.1,4220 4786.1,3137.11 ccw(c4736.89,3137.11) 4737.1,3087.9 3654.21,3087.9 ccw(c3654.21,3137.11)
GND on Bottom Layer "GND_L02_P001" (solid, remove dead copper, pour order 1): 3605,3136.9 3605,4219.79 ccw(c3654.21,4219.79) 3654,4269 4736.89,4269 ccw(c4736.89,4219.79) 4786.1,4220 4786.1,3137.11 ccw(c4736.89,3137.11) 4737.1,3087.9 3654.21,3087.9 ccw(c3654.21,3137.11)

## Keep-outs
Keep-Out Layer:
  the board outline again, w10

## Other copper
Top Layer:
  pour cut-out: 4648.31,3137.11 ccw(c4736.89,3137.11) 4736.89,3048.53 ccw(c4736.89,3137.11) 4825.47,3137.11 ccw(c4736.89,3137.11) 4736.89,3225.69 ccw(c4736.89,3137.11)
  pour cut-out: 3565.63,3137.11 ccw(c3654.21,3137.11) 3654.21,3048.53 ccw(c3654.21,3137.11) 3742.8,3137.11 ccw(c3654.21,3137.11) 3654.21,3225.69 ccw(c3654.21,3137.11)
  pour cut-out: 4648.31,4219.79 ccw(c4736.89,4219.79) 4736.89,4131.2 ccw(c4736.89,4219.79) 4825.47,4219.79 ccw(c4736.89,4219.79) 4736.89,4308.37 ccw(c4736.89,4219.79)
  pour cut-out: 3654.21,4131.2 cw(c3654.21,4219.79) 3565.63,4219.79 cw(c3654.21,4219.79) 3654.21,4308.37 cw(c3654.21,4219.79) 3742.8,4219.79 cw(c3654.21,4219.79)
Bottom Layer:
  pour cut-out: 3654.21,4131.2 cw(c3654.21,4219.79) 3565.63,4219.79 cw(c3654.21,4219.79) 3654.21,4308.37 cw(c3654.21,4219.79) 3742.8,4219.79 cw(c3654.21,4219.79)
  pour cut-out: 4648.31,4219.79 ccw(c4736.89,4219.79) 4736.89,4131.2 ccw(c4736.89,4219.79) 4825.47,4219.79 ccw(c4736.89,4219.79) 4736.89,4308.37 ccw(c4736.89,4219.79)
  pour cut-out: 4648.31,3137.11 ccw(c4736.89,3137.11) 4736.89,3048.53 ccw(c4736.89,3137.11) 4825.47,3137.11 ccw(c4736.89,3137.11) 4736.89,3225.69 ccw(c4736.89,3137.11)
  pour cut-out: 3565.63,3137.11 ccw(c3654.21,3137.11) 3654.21,3048.53 ccw(c3654.21,3137.11) 3742.8,3137.11 ccw(c3654.21,3137.11) 3654.21,3225.69 ccw(c3654.21,3137.11)

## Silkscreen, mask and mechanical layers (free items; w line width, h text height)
Bottom Overlay:
  text "3" at 3891.15,4154.39 h60 r180
  text "G" at 3942.15,4154.39 h60 r180
  text "C" at 3991.15,4154.39 h60 r180
  text "D" at 4040.07,4154.39 h60 r180
  text "T" at 4118.93,4154.39 h60 r180
  text "V" at 4375.19,4150.39 h60 r180
  text "G" at 4424.19,4150.39 h60 r180
  text "D" at 4475.07,4150.39 h60 r180
  text "C" at 4529.07,4150.39 h60 r180
  text "L" at 4179.58,3296.73 h60
  text "V" at 4031.81,3295.61 h60
  text "G" at 4081.81,3295.61 h60
  text "H" at 4133.85,3295.61 h60
Mechanical 15:
  circle w10: c4459,3165 r157.48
